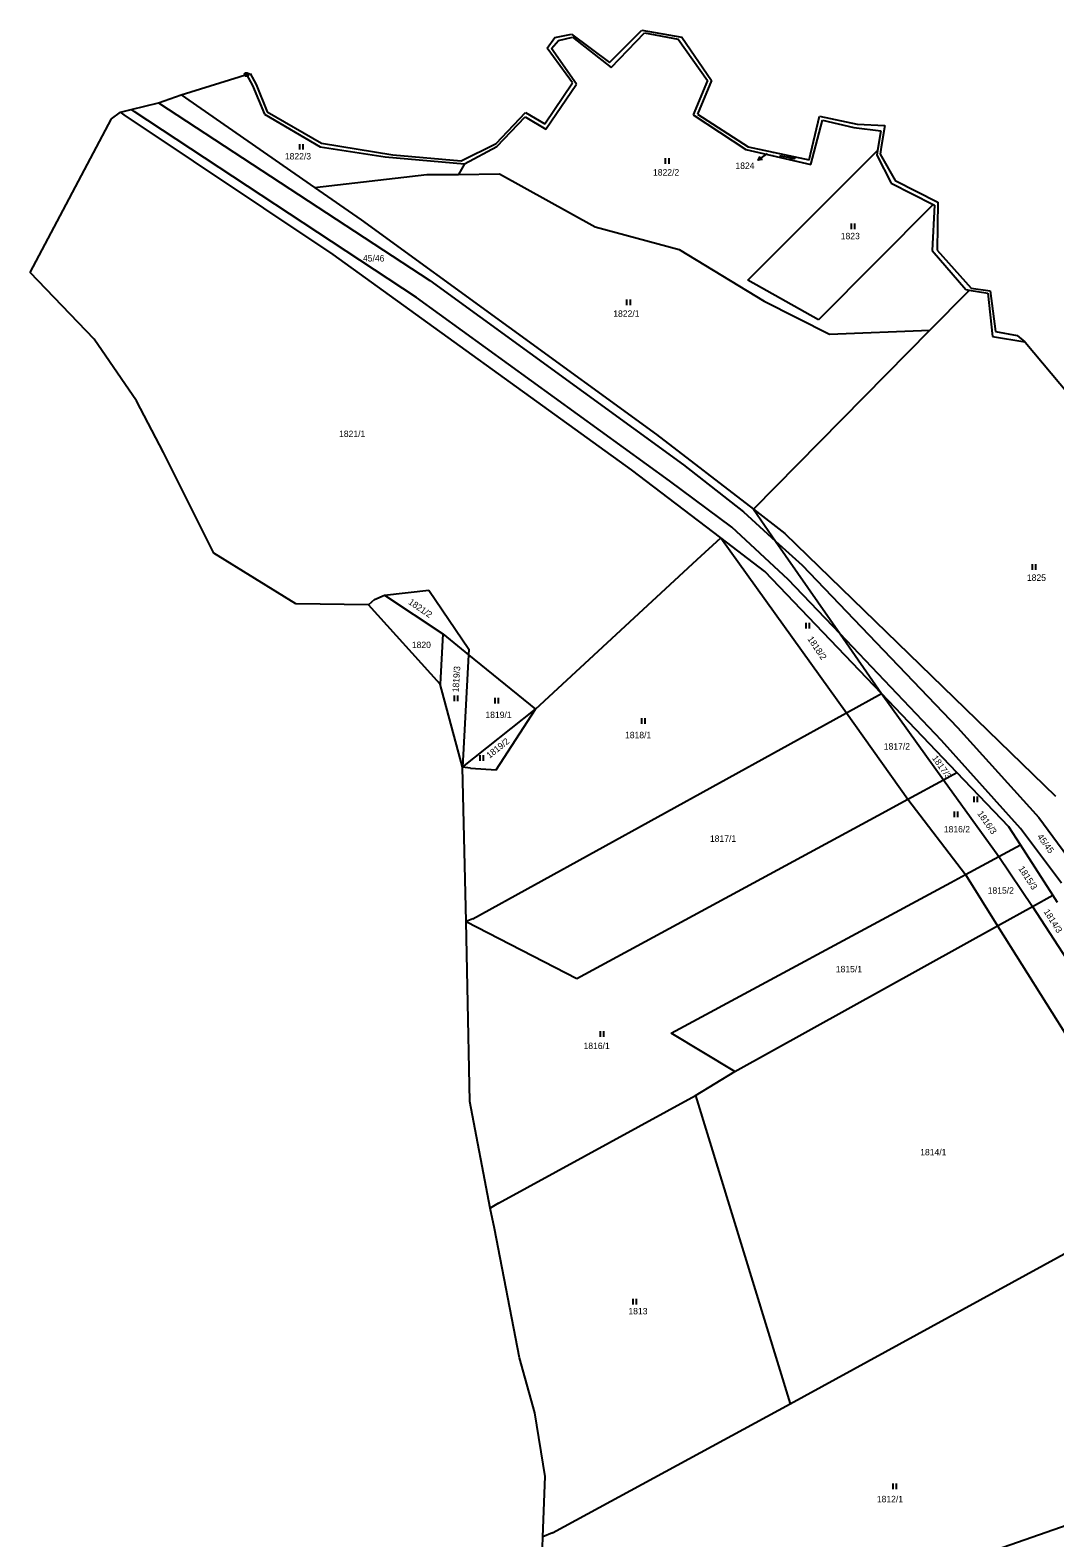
# Model space of a CAD drawing. Extents: x -609861 to -605046, y -1120287 to -1116307.
# Drawn here: x -609141.7 to -608869.6, y -1116873.3 to -1116473.1 of the extents above; entities that cross this region are included whole.
import ezdxf

# ---------------------------------------------------------------- set-up
doc = ezdxf.new("R2010")
doc.units = 0
for name, color, linetype in [('Vrstva 1', 7, 'Continuous'), ('Vrstva 2', 7, 'Continuous'), ('Vrstva 3', 7, 'Continuous'), ('Vrstva 4', 7, 'Continuous'), ('Vrstva 7', 7, 'Continuous'), ('Vrstva 8', 7, 'Continuous')]:
    doc.layers.add(name, color=color, linetype=linetype)

msp = doc.modelspace()

# ---------------------------------------------------------------- linework, layer by layer
at = {"layer": 'Vrstva 1'}
for p, q in [((-609004.39, -1116477.89), (-609002.41, -1116474.99)), ((-609003.22, -1116477.92), (-609001.38, -1116475.79)), ((-609002.41, -1116474.99), (-608997.98, -1116474.13)), ((-609001.38, -1116475.79), (-608997.7, -1116474.94)), ((-608997.98, -1116474.13), (-608987.86, -1116481.63)), ((-608997.7, -1116474.94), (-608987.43, -1116483.03)), ((-608987.86, -1116481.63), (-608979.24, -1116473.08)), ((-608987.43, -1116483.03), (-608978.54, -1116473.81)), ((-608979.24, -1116473.08), (-608968.7, -1116474.98)), ((-608978.54, -1116473.81), (-608969.64, -1116475.51)), ((-608969.64, -1116475.51), (-608961.82, -1116486.43)), ((-608968.7, -1116474.98), (-608960.82, -1116486.41)), ((-608997.7, -1116487.04), (-609004.39, -1116477.89)), ((-608996.63, -1116487.43), (-609003.22, -1116477.92)), ((-609101.57, -1116490.29), (-609086.21, -1116485.48)), ((-609086.21, -1116485.48), (-609084.21, -1116484.85)), ((-609084.21, -1116484.85), (-609083.26, -1116484.55)), ((-609084.21, -1116484.85), (-609082.65, -1116487.73)), ((-609083.26, -1116484.55), (-609081.67, -1116487.54)), ((-609082.65, -1116487.73), (-609079.42, -1116495.37)), ((-609081.67, -1116487.54), (-609078.73, -1116494.73)), ((-609005.01, -1116497.91), (-608997.7, -1116487.04)), ((-609004.75, -1116499.35), (-608996.63, -1116487.43)), ((-608961.82, -1116486.43), (-608965.66, -1116495.52)), ((-608960.82, -1116486.41), (-608964.51, -1116495.34)), ((-609107.54, -1116492.38), (-609101.57, -1116490.29)), ((-609101.57, -1116490.29), (-609066.15, -1116514.82)), ((-609120.04, -1116496.66), (-609117.71, -1116494.88)), ((-609117.71, -1116494.88), (-609114.82, -1116494.17)), ((-609116.68, -1116495.57), (-609117.71, -1116494.88)), ((-609061.26, -1116532.62), (-609116.68, -1116495.57)), ((-609114.82, -1116494.17), (-609107.54, -1116492.38)), ((-609079.42, -1116495.37), (-609064.7, -1116504.03)), ((-609078.73, -1116494.73), (-609064.32, -1116503.11)), ((-609017.96, -1116503.16), (-609010.19, -1116494.96)), ((-609017.74, -1116503.94), (-609010.27, -1116496.08)), ((-609010.27, -1116496.08), (-609004.75, -1116499.35)), ((-609010.19, -1116494.96), (-609005.01, -1116497.91)), ((-608965.66, -1116495.52), (-608951.71, -1116504.74)), ((-608964.51, -1116495.34), (-608951.02, -1116504.08)), ((-608934.85, -1116507.51), (-608932.11, -1116495.92)), ((-608932.11, -1116495.92), (-608922.1, -1116498.03)), ((-609141.65, -1116537.39), (-609120.04, -1116496.66)), ((-608934.38, -1116508.71), (-608931.31, -1116496.94)), ((-608931.31, -1116496.94), (-608923.04, -1116498.92)), ((-608923.04, -1116498.92), (-608915.83, -1116499.77)), ((-608922.1, -1116498.03), (-608914.81, -1116498.39)), ((-608915.83, -1116499.77), (-608916.7, -1116505.06)), ((-608914.81, -1116498.39), (-608915.74, -1116504.11)), ((-609064.7, -1116504.03), (-609047.38, -1116506.73)), ((-609064.32, -1116503.11), (-609045.36, -1116506.19)), ((-609027.26, -1116507.77), (-609017.96, -1116503.16)), ((-609026.34, -1116508.54), (-609017.74, -1116503.94)), ((-608951.02, -1116504.08), (-608934.85, -1116507.51)), ((-608915.74, -1116504.11), (-608916.05, -1116505.98)), ((-609047.38, -1116506.73), (-609026.34, -1116508.54)), ((-609045.36, -1116506.19), (-609027.26, -1116507.77)), ((-608951.71, -1116504.74), (-608934.38, -1116508.71)), ((-608951.15, -1116539.4), (-608916.7, -1116505.06)), ((-608916.7, -1116505.06), (-608916.9, -1116506.3)), ((-608916.9, -1116506.3), (-608913.07, -1116513.68)), ((-608916.05, -1116505.98), (-608912.08, -1116513.01)), ((-609066.15, -1116514.82), (-609036.35, -1116511.42)), ((-609036.35, -1116511.42), (-609027.96, -1116511.39)), ((-609026.34, -1116508.54), (-609027.96, -1116511.39)), ((-609027.96, -1116511.39), (-609017.03, -1116511.22)), ((-609017.03, -1116511.22), (-608991.7, -1116525.32)), ((-609066.15, -1116514.82), (-609053.75, -1116523.4)), ((-608913.07, -1116513.68), (-608901.93, -1116519.32)), ((-608912.08, -1116513.01), (-608900.67, -1116518.73)), ((-608901.93, -1116519.32), (-608932.37, -1116550)), ((-608901.57, -1116519.5), (-608902.19, -1116531.56)), ((-608901.93, -1116519.32), (-608901.57, -1116519.5)), ((-608900.67, -1116518.73), (-608900.91, -1116531.45)), ((-609053.75, -1116523.4), (-608975.37, -1116580.39)), ((-608991.7, -1116525.32), (-608969.38, -1116531.28)), ((-608969.38, -1116531.28), (-608946.84, -1116544.99)), ((-608902.19, -1116531.56), (-608893.29, -1116541.92)), ((-608900.91, -1116531.45), (-608891.82, -1116541.55)), ((-608982.03, -1116589.77), (-609061.26, -1116532.62)), ((-609124.64, -1116555.13), (-609141.65, -1116537.39)), ((-608932.37, -1116550), (-608951.15, -1116539.4)), ((-608892.78, -1116542.52), (-608902.82, -1116552.71)), ((-608893.29, -1116541.92), (-608892.35, -1116542.08)), ((-608892.35, -1116542.08), (-608892.78, -1116542.52)), ((-608892.35, -1116542.08), (-608887.47, -1116542.91)), ((-608891.82, -1116541.55), (-608886.83, -1116542.3)), ((-608887.47, -1116542.91), (-608886.24, -1116554.41)), ((-608886.83, -1116542.3), (-608885.44, -1116553.07)), ((-608946.84, -1116544.99), (-608929.45, -1116553.73)), ((-609113.44, -1116571.44), (-609124.64, -1116555.13)), ((-608902.82, -1116552.71), (-608949.65, -1116600.25)), ((-608929.45, -1116553.73), (-608902.82, -1116552.71)), ((-608886.24, -1116554.41), (-608877.65, -1116555.83)), ((-608885.44, -1116553.07), (-608879.67, -1116554.12)), ((-608879.67, -1116554.12), (-608877.65, -1116555.83)), ((-608877.65, -1116555.83), (-608877.57, -1116555.93)), ((-608877.57, -1116555.93), (-608866, -1116569.59)), ((-609106.24, -1116585.21), (-609113.44, -1116571.44)), ((-608975.37, -1116580.39), (-608949.65, -1116600.25)), ((-609092.9, -1116611.89), (-609106.24, -1116585.21)), ((-608958.33, -1116607.82), (-608982.03, -1116589.77)), ((-608949.65, -1116600.25), (-608943.77, -1116608.71)), ((-608949.65, -1116600.25), (-608941.31, -1116606.69)), ((-608964.58, -1116613.6), (-608958.33, -1116607.82)), ((-608958.33, -1116607.82), (-608924.92, -1116654.26)), ((-608946.63, -1116616.73), (-608958.33, -1116607.82)), ((-608941.31, -1116606.69), (-608869.47, -1116676.41)), ((-609071.13, -1116625.37), (-609092.9, -1116611.89)), ((-608943.77, -1116608.71), (-608926.66, -1116633.33)), ((-609007.5, -1116653.33), (-608964.58, -1116613.6)), ((-608915.66, -1116649.15), (-608946.63, -1116616.73)), ((-609050.28, -1116624.21), (-609051.81, -1116625.65)), ((-609050.28, -1116624.21), (-609047.6, -1116623.04)), ((-609047.6, -1116623.04), (-609035.83, -1116621.76)), ((-609047.6, -1116623.04), (-609032.1, -1116633.31)), ((-609035.83, -1116621.76), (-609025.23, -1116637.36)), ((-609051.81, -1116625.65), (-609071.13, -1116625.37)), ((-609032.8, -1116646.65), (-609051.81, -1116625.65)), ((-609032.1, -1116633.31), (-609032.8, -1116646.65)), ((-609032.1, -1116633.31), (-609025.31, -1116638.84)), ((-608926.66, -1116633.33), (-608915.66, -1116649.15)), ((-609025.31, -1116638.84), (-609026.9, -1116668.74)), ((-609025.23, -1116637.36), (-609025.31, -1116638.84)), ((-609025.31, -1116638.84), (-609007.5, -1116653.33)), ((-609026.9, -1116668.74), (-609032.8, -1116646.65)), ((-608924.92, -1116654.26), (-608915.66, -1116649.15)), ((-608915.66, -1116649.15), (-608899.2, -1116672.03)), ((-608895.64, -1116670.1), (-608915.66, -1116649.15)), ((-609026.9, -1116668.74), (-609007.5, -1116653.33)), ((-609024.14, -1116708.92), (-608925.91, -1116654.8)), ((-609017.98, -1116669.44), (-609007.5, -1116653.33)), ((-608925.91, -1116654.8), (-608924.92, -1116654.26)), ((-608924.92, -1116654.26), (-608908.65, -1116677.16)), ((-609025.95, -1116709.69), (-609026.9, -1116668.74)), ((-609024.76, -1116668.97), (-609026.9, -1116668.74)), ((-609024.76, -1116668.97), (-609017.98, -1116669.44)), ((-608908.65, -1116677.16), (-608899.2, -1116672.03)), ((-608899.2, -1116672.03), (-608895.64, -1116670.1)), ((-608899.2, -1116672.03), (-608884.52, -1116692.39)), ((-608881.87, -1116684.52), (-608895.64, -1116670.1)), ((-608916.67, -1116681.51), (-608908.65, -1116677.16)), ((-608908.65, -1116677.16), (-608893.35, -1116697.15)), ((-608996.53, -1116724.83), (-608916.67, -1116681.51)), ((-608878.8, -1116689.31), (-608881.87, -1116684.52)), ((-608884.52, -1116692.39), (-608878.8, -1116689.31)), ((-608870.21, -1116702.68), (-608878.8, -1116689.31)), ((-608893.35, -1116697.15), (-608884.52, -1116692.39)), ((-608884.52, -1116692.39), (-608875.59, -1116705.66)), ((-608971.5, -1116739.26), (-608897.3, -1116699.28)), ((-608897.3, -1116699.28), (-608893.35, -1116697.15)), ((-608893.35, -1116697.15), (-608884.84, -1116710.8)), ((-608875.59, -1116705.66), (-608870.21, -1116702.68)), ((-608868.95, -1116704.65), (-608870.21, -1116702.68)), ((-608884.84, -1116710.8), (-608875.59, -1116705.66)), ((-608875.59, -1116705.66), (-608865.39, -1116721.3)), ((-609024.14, -1116708.92), (-609025.95, -1116709.69)), ((-609025.59, -1116726.97), (-609025.95, -1116709.69)), ((-609025.95, -1116709.69), (-608996.53, -1116724.83)), ((-608954.57, -1116749.5), (-608884.84, -1116710.8)), ((-608884.84, -1116710.8), (-608865.51, -1116741.58)), ((-609024.98, -1116757.48), (-609025.59, -1116726.97)), ((-608954.57, -1116749.5), (-608971.5, -1116739.26)), ((-608965.04, -1116755.86), (-608954.57, -1116749.5)), ((-609017.34, -1116784.46), (-608965.04, -1116755.86)), ((-608965.04, -1116755.86), (-608939.88, -1116837.71)), ((-609019.56, -1116785.74), (-609024.98, -1116757.48)), ((-609017.34, -1116784.46), (-609019.56, -1116785.74)), ((-609018.39, -1116791.11), (-609019.56, -1116785.74)), ((-608939.88, -1116837.71), (-608845.21, -1116785.85)), ((-609011.79, -1116825.45), (-609018.39, -1116791.11)), ((-609007.66, -1116840.07), (-609011.79, -1116825.45)), ((-609004.9, -1116856.95), (-609007.66, -1116840.07)), ((-609003.01, -1116871.93), (-608939.88, -1116837.71)), ((-609005.57, -1116873.02), (-609004.9, -1116856.95)), ((-608908.69, -1116884.53), (-608838.32, -1116859.96)), ((-609003.01, -1116871.93), (-609005.57, -1116873.02)), ((-609005.66, -1116875.83), (-609005.57, -1116873.02))]:
    msp.add_line(p, q, dxfattribs=at)
at = {"layer": 'Vrstva 3'}
for p, q in [((-609070.17, -1116503.3), (-609070.17, -1116504.8)), ((-609069.17, -1116504.8), (-609069.17, -1116503.3)), ((-608973.05, -1116507.08), (-608973.05, -1116508.58)), ((-608972.05, -1116508.58), (-608972.05, -1116507.08)), ((-608942.776, -1116506.31), (-608938.664, -1116507.17)), ((-608923.73, -1116524.38), (-608923.73, -1116525.88)), ((-608922.73, -1116525.88), (-608922.73, -1116524.38)), ((-608983.32, -1116544.59), (-608983.32, -1116546.09)), ((-608982.32, -1116546.09), (-608982.32, -1116544.59)), ((-608875.66, -1116614.8), (-608875.66, -1116616.3)), ((-608874.66, -1116616.3), (-608874.66, -1116614.8)), ((-608935.77, -1116630.38), (-608935.77, -1116631.88)), ((-608934.77, -1116631.88), (-608934.77, -1116630.38)), ((-609029.1, -1116649.64), (-609029.1, -1116651.14)), ((-609028.1, -1116651.14), (-609028.1, -1116649.64)), ((-609018.33, -1116650.33), (-609018.33, -1116651.83)), ((-609017.33, -1116651.83), (-609017.33, -1116650.33)), ((-608979.36, -1116655.68), (-608979.36, -1116657.18)), ((-608978.36, -1116657.18), (-608978.36, -1116655.68)), ((-609022.31, -1116665.51), (-609022.31, -1116667.01)), ((-609021.31, -1116667.01), (-609021.31, -1116665.51)), ((-608891.15, -1116676.45), (-608891.15, -1116677.95)), ((-608890.15, -1116677.95), (-608890.15, -1116676.45)), ((-608896.38, -1116680.49), (-608896.38, -1116681.99)), ((-608895.38, -1116681.99), (-608895.38, -1116680.49)), ((-608990.35, -1116738.77), (-608990.35, -1116740.27)), ((-608989.35, -1116740.27), (-608989.35, -1116738.77)), ((-608981.68, -1116809.8), (-608981.68, -1116811.3)), ((-608980.68, -1116811.3), (-608980.68, -1116809.8)), ((-608912.67, -1116858.81), (-608912.67, -1116860.31)), ((-608911.67, -1116860.31), (-608911.67, -1116858.81))]:
    msp.add_line(p, q, dxfattribs=at)
msp.add_lwpolyline([(-608939.963, -1116506.541), (-608938.664, -1116507.17), (-608940.106, -1116507.226)], dxfattribs=at)
at = {"layer": 'Vrstva 4'}
for p, q in [((-609114.08, -1116494.66), (-609114.82, -1116494.17)), ((-609039.12, -1116544.04), (-609114.08, -1116494.66)), ((-609107.54, -1116492.38), (-609035.54, -1116539.54)), ((-609035.54, -1116539.54), (-608968.2, -1116588.47)), ((-608971.92, -1116592.72), (-609039.12, -1116544.04)), ((-608968.2, -1116588.47), (-608952.3, -1116600.93)), ((-608955.41, -1116605.04), (-608971.92, -1116592.72)), ((-608952.3, -1116600.93), (-608943.77, -1116608.71)), ((-608940.45, -1116618.87), (-608955.41, -1116605.04)), ((-608943.77, -1116608.71), (-608936.74, -1116615.12)), ((-608936.74, -1116615.12), (-608895.45, -1116658.16)), ((-608926.66, -1116633.33), (-608940.45, -1116618.87)), ((-608899.7, -1116661.59), (-608926.66, -1116633.33)), ((-608895.45, -1116658.16), (-608873.87, -1116682.09)), ((-608878.8, -1116684.95), (-608899.7, -1116661.59)), ((-608873.87, -1116682.09), (-608862.5, -1116697.52)), ((-608867.91, -1116699.46), (-608878.8, -1116684.95))]:
    msp.add_line(p, q, dxfattribs=at)
at = {"layer": 'Vrstva 7'}
msp.add_line((-608948.389, -1116507.621), (-608945.96, -1116505.86), dxfattribs=at)
msp.add_lwpolyline([(-608947.286, -1116507.439), (-608948.389, -1116507.621), (-608947.873, -1116506.629)], dxfattribs=at)
at = {"layer": 'Vrstva 8'}
msp.add_line((-609084.33, -1116484.85), (-609084.09, -1116484.85), dxfattribs=at)
msp.add_lwpolyline([(-609084.06, -1116484.37), (-609083.81, -1116484.55), (-609083.71, -1116484.84), (-609083.81, -1116485.13), (-609084.06, -1116485.31), (-609084.37, -1116485.31), (-609084.62, -1116485.13), (-609084.72, -1116484.84), (-609084.62, -1116484.55), (-609084.37, -1116484.37)], close=True, dxfattribs=at)

# ---------------------------------------------------------------- texts
at = {"layer": 'Vrstva 2'}
for s, p in [('1822/3', (-609074.037, -1116507.4)), ('1822/2', (-608976.317, -1116511.67)), ('1823', (-608926.477, -1116528.58)), ('45/46', (-609053.303, -1116534.48)), ('1822/1', (-608986.867, -1116549.17)), ('1821/1', (-609059.647, -1116581.07)), ('1825', (-608877.067, -1116619.25)), ('1820', (-609040.327, -1116637.09)), ('1819/1', (-609020.807, -1116655.66)), ('1818/1', (-608983.737, -1116661.02)), ('1817/2', (-608915.057, -1116664.03)), ('1816/2', (-608899.117, -1116686.02)), ('1817/1', (-608961.207, -1116688.52)), ('1815/2', (-608887.477, -1116702.27)), ('1815/1', (-608927.787, -1116723.14)), ('1816/1', (-608994.757, -1116743.51)), ('1814/1', (-608905.387, -1116771.73)), ('1813', (-608982.847, -1116813.93)), ('1812/1', (-608916.897, -1116863.81))]:
    msp.add_text(s, height=1.7, dxfattribs=at).set_placement(p)
for s, height, rotation, p in [('1824', 0.2, 347.38431, (-608944.915, -1116505.92)), ('1821/2', 1.7, 325.7838, (-609041.415, -1116625.261)), ('1818/2', 1.7, 304.18329, (-608935.409, -1116634.675)), ('1819/3', 1.7, 86.40204, (-609027.895, -1116648.878)), ('1819/2', 1.7, 38.67465, (-609019.693, -1116666.485)), ('1817/3', 1.7, 305.10003, (-608902.344, -1116666.291)), ('1816/3', 1.7, 305.10003, (-608890.314, -1116681.021)), ('45/45', 1.7, 306.01676, (-608874.44, -1116687.172)), ('1815/3', 1.7, 303.32386, (-608879.404, -1116695.618)), ('1814/3', 1.7, 302.40713, (-608872.69, -1116707.032))]:
    msp.add_text(s, height=height, rotation=rotation, dxfattribs=at).set_placement(p)
at = {"layer": 'Vrstva 7'}
msp.add_text('1824', height=1.7, dxfattribs=at).set_placement((-608954.43, -1116509.91))

doc.saveas('drawing.dxf')
